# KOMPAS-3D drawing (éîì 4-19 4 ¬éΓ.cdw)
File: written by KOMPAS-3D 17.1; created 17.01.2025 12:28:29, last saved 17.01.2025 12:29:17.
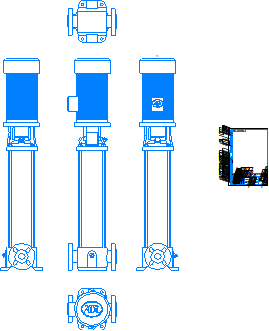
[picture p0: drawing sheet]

Sheet 1: A4, portrait

Title block, sheet 1: name: ВМН 4-19 4 кВт; designation: ВМН 4-19 4 кВт; material: Сталь 10  ГОСТ 1050-2013; mass: 53,4; sheets: 1; sheet format: A4; stored path: \\adlc.lan\data\АДЛ_ПКД\3D-модели\ADL production\Насосы ГРАНПАМП\Насосы ВМН\ВМН4\KOMPAS 3D\ВМН 4-19 4 кВт.cdw

Views: Вид 1, Спереди, Проекционный вид 2, Проекционный вид 3, Проекционный вид 4, Проекционный вид 5
Referenced files in \\adlc.lan\data\АДЛ_ПКД\3D-модели\ADL production\Насосы ГРАНПАМП\Насосы ВМН\ВМН4\KOMPAS 3D\: ВМН 4-19 4 кВт.m3d
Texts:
  Andrey
  АДЛ
Dimensions and other numbers on the sheet: 1:1; 1; 53,4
